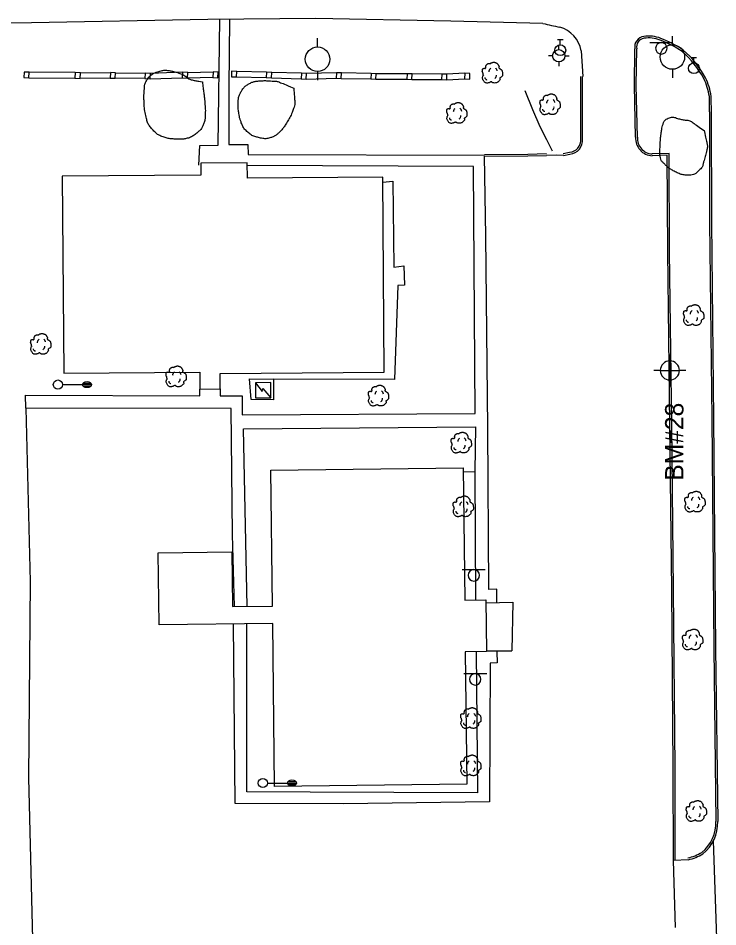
# Model space of a CAD drawing. Extents: x 2145380 to 2156929, y 139568 to 149130.
# Drawn here: x 2150488.9 to 2150717.1, y 141353.6 to 141649.9 of the extents above; entities that cross this region are included whole.
import ezdxf

# ---------------------------------------------------------------- set-up
doc = ezdxf.new("R2010")
doc.units = 0
for name, color, linetype in [('Default', 7, 'Continuous'), ('SURV_Benchmark', 7, 'Continuous'), ('SURV_Text', 7, 'Continuous'), ('TOPO_Asphalt', 7, 'Continuous'), ('TOPO_Building', 7, 'Continuous'), ('TOPO_Concrete', 7, 'Continuous'), ('TOPO_Curb Back', 7, 'Continuous'), ('TOPO_Flowline', 7, 'Continuous'), ('TOPO_Light Pole', 7, 'Continuous'), ('TOPO_Misc', 7, 'Continuous'), ('TOPO_Power Pole', 7, 'Continuous'), ('TOPO_Sidewalk', 7, 'Continuous'), ('TOPO_Sign', 7, 'Continuous'), ('TOPO_Tree', 7, 'Continuous'), ('TOPO_Tree Line', 7, 'Continuous'), ('TOPO_Wall Freestanding', 7, 'Continuous'), ('TOPO_Water Fire Hydrant', 7, 'Continuous'), ('TOPO_Water Valve', 7, 'Continuous')]:
    doc.layers.add(name, color=color, linetype=linetype)

# ---------------------------------------------------------------- blocks, each defined once
blk = doc.blocks.new('LP')
at = {"layer": 'TOPO_Light Pole'}
blk.add_line((3.81, 0), (20.32, 0), dxfattribs=at)
for points in [[(20.32, 0), (27.94, 0)], [(20.32, 0), (23.5, 0)], [(20.83, 1.27), (27.43, 1.27)], [(20.83, 1.27), (23.5, 1.27)], [(23.71, 1.27), (27.43, 1.27)], [(23.71, 0), (27.94, 0)], [(20.83, -1.27), (27.43, -1.27)], [(20.83, -1.27), (23.5, -1.27)], [(23.71, -1.27), (27.43, -1.27)]]:
    blk.add_lwpolyline(points, dxfattribs=at)
blk.add_circle((0, 0), 3.81, dxfattribs=at)
blk.add_ellipse((24.13, 0), major_axis=(3.81, 0), ratio=0.666667, dxfattribs=at)
blk = doc.blocks.new('FIRHYD')
at = {"layer": 'TOPO_Water Fire Hydrant'}
for p, q in [((0, 10.2), (0, 17.3)), ((10.2, 0), (17.3, 0)), ((-10.2, 0), (-17.3, 0)), ((0, -10.2), (0, -17.3))]:
    blk.add_line(p, q, dxfattribs=at)
blk.add_circle((0, 0), 10.2, dxfattribs=at)
blk = doc.blocks.new('TREE')
at = {"layer": 'TOPO_Tree'}
for points in [[(-14.1, -0.4), (-14.2, 0.5), (-14.4, 1.4), (-14.6, 2.3), (-14.8, 3.2), (-15.5, 4), (-15.7, 4.9), (-15.8, 5.6), (-15.7, 6.3), (-15.7, 7), (-15.6, 7.9), (-15.7, 8.8), (-15.1, 9.7), (-14.6, 10.4), (-13.8, 10.5), (-13, 10.7), (-12.2, 11), (-11.1, 10), (-10.4, 10.7), (-9.4, 11.7), (-10.3, 13.3), (-9.8, 14.4), (-9.6, 15.1), (-9.3, 15.9), (-8.8, 16.5), (-8.2, 17.3), (-7.5, 17.7), (-6.7, 18.1), (-6.1, 18.4), (-5.6, 18.6), (-5.1, 18.7), (-4.5, 18.7), (-4, 18.5), (-3.5, 18.1)], [(-3.5, 17.6), (-3.1, 18.3), (-2.6, 18.8), (-1.9, 19.2), (-1, 19.7), (-0.2, 20), (0.7, 20.2), (1.6, 20.5), (2.5, 20.8), (3.4, 20.8), (4.1, 20.7), (4.8, 20.5), (5.5, 20.2), (6.4, 19.9), (7.3, 19.7), (8.2, 19.2), (9.4, 18.4), (10, 17.2), (10.8, 16), (11.2, 15.3), (11.6, 14.6), (11.9, 13.9), (12.2, 13.1), (11.4, 12), (11.9, 11.2), (12, 11), (12.2, 10.9), (12.4, 10.7), (12.9, 10.4), (13.5, 10), (14, 9.7), (14.7, 9.2), (15.4, 8.7), (16.1, 8.1), (16.7, 7.5), (16.9, 6.7), (17.1, 6), (17.6, 4.4), (17.7, 2.8), (17.7, 1.2), (17.7, -0.2), (17.8, -2.2), (16.6, -3), (15.5, -3.8), (14.3, -4.6), (13.2, -5.3)], [(13.2, -5.3), (13.3, -5.8), (13.4, -6.3), (13.4, -6.7), (13.8, -8.5), (12.2, -10), (10.8, -11.5), (10, -12.3), (9.1, -12.8), (8.2, -13.1), (6, -13.8), (3.3, -13.6), (1.3, -13.1), (0.5, -12.9), (-0.1, -11.4), (-0.8, -11.5), (-2, -11.6), (-3.3, -12.8), (-4.5, -13.1), (-6.1, -13.5), (-7.8, -14), (-9.3, -13.6), (-11.4, -13.1), (-12.8, -11.4), (-14.1, -9.4), (-15.3, -7.3), (-15.6, -5.1), (-15.1, -3), (-14.9, -1.9), (-13.9, -0.8), (-13.5, 0.1)], [(-4.2, 5.1), (-4.5, 6.1), (-4.3, 7.2), (-3.8, 8.2), (-3.3, 9.3), (-2.7, 10.3), (-1.6, 11)], [(5.9, 11.2), (6.5, 10.7), (7, 10.2), (7.4, 9.5), (7.9, 8.6), (8.3, 7.6), (8.5, 6.6)], [(-11.4, -4.5), (-11.5, -5.4), (-11, -6.3), (-10.1, -7.2), (-9.3, -8), (-8.5, -8.3), (-7.7, -8.1)], [(4.8, -6.3), (5.7, -5.7), (6.3, -4.9), (6.8, -3.9), (7.4, -2.8), (7.6, -1.7), (7.5, -0.6)]]:
    blk.add_open_spline(points, degree=3, dxfattribs=at)
blk = doc.blocks.new('POWPOL')
at = {"layer": 'TOPO_Power Pole'}
for p, q in [((0, 10.16), (0, 17.34)), ((0, -10.16), (0, -17.34))]:
    blk.add_line(p, q, dxfattribs=at)
blk.add_circle((0, 0), 10.16, dxfattribs=at)
blk = doc.blocks.new('WATVAL')
at = {"layer": 'Default'}
for p, q in [((-2.25, 9), (2.25, 9)), ((0, 4.5), (0, 9))]:
    blk.add_line(p, q, dxfattribs=at)
blk.add_circle((0, 0), 4.5, dxfattribs=at)
blk = doc.blocks.new('BM')
at = {"layer": 'SURV_Benchmark'}
for p, q in [((0, 2.49), (0, 4.15)), ((-2.49, 0), (-4.16, 0)), ((4.16, 0), (2.49, 0)), ((0, -4.16), (0, -2.49))]:
    blk.add_line(p, q, dxfattribs=at)
for points in [[(0, 2.49), (0, 2.49), (0, 0), (2.49, 0), (2.49, 0), (2.49, 0)], [(0, 2.49), (0, 2.49), (0, 0), (2.49, 0), (2.49, 0), (2.49, 0), (2.49, 0)], [(-2.5, 0), (-2.49, 0), (0, 0), (0, -2.49), (0, -2.49)], [(-2.5, 0), (-2.49, 0), (0, 0), (0, -2.49), (0, -2.49)]]:
    blk.add_lwpolyline(points, dxfattribs=at)
for start, end in [(90.0638, 180.0068), (0.0638, 90.0068), (0.0638, 90.0068), (180.0638, 270.0068), (180.0638, 270.0068), (269.9472, 359.9927)]:
    blk.add_arc((0, 0), 2.5, start, end, dxfattribs=at)

msp = doc.modelspace()

# ---------------------------------------------------------------- linework, layer by layer
at = {"layer": 'TOPO_Asphalt'}
for p, q in [((2150650.27, 141459.46), (2150649.88, 141443.53)), ((2150717.09, 141340.93), (2150715.71, 141381.66)), ((2150707.51, 141375.44), (2150702.61, 141375.22)), ((2150703.25, 141353.37), (2150702.61, 141375.22))]:
    msp.add_line(p, q, dxfattribs=at)
for points in [[(2150173.54, 141646.08), (2150188.55, 141646.69), (2150232.35, 141647.37), (2150285.09, 141647.5), (2150334.75, 141647.84), (2150374.92, 141648.5), (2150418.39, 141648.61), (2150460.06, 141648.31), (2150493.23, 141648.46), (2150550.78, 141649.53), (2150586.03, 141649.89), (2150630.05, 141649.07), (2150660.05, 141648.21)], [(2150672.55, 141639.26), (2150673.03, 141630.89)], [(2150645.07, 141459.3), (2150645.04, 141463.69), (2150642.45, 141463.61), (2150642.12, 141516.18), (2150641.45, 141578.89), (2150641.05, 141604.88)], [(2150666.75, 141605.15), (2150664.55, 141605.2), (2150661.27, 141605.11)], [(2150559.44, 141458.02), (2150558.77, 141481.57), (2150558.4, 141522.63), (2150491.39, 141522.67), (2150492.76, 141466.17), (2150492.26, 141402.2), (2150493.85, 141336.4), (2150493.9, 141335.26), (2150500.21, 141335.3)], [(2150645.07, 141443.2), (2150645.18, 141439.69), (2150642.81, 141439.61), (2150642.68, 141394.39), (2150595.05, 141393.64), (2150559.62, 141393.75), (2150559.16, 141452.36)]]:
    msp.add_lwpolyline(points, dxfattribs=at)
for centre, radius, start, end in [((2150680.45, 141727.07), 81.46, 255.4956, 259.4775), ((2150662.63, 141637.31), 10.12, 11.1443, 73.0742)]:
    msp.add_arc(centre, radius, start, end, dxfattribs=at)
at = {"layer": 'TOPO_Building'}
for points in [[(2150554.78, 141528.99), (2150554.74, 141534.03), (2150608.32, 141534.44), (2150607.83, 141598.09), (2150563.64, 141597.76), (2150563.6, 141602.76), (2150548.41, 141602.64), (2150548.44, 141598.72), (2150503.24, 141598.38), (2150503.72, 141534.09), (2150548.12, 141534.43), (2150548.16, 141528.94)], [(2150635.19, 141400.05), (2150572.54, 141399.32), (2150571.91, 141452.51), (2150534.84, 141452.08), (2150534.56, 141475.56), (2150558.55, 141475.84), (2150558.75, 141458.01), (2150571.79, 141458.16), (2150571.27, 141502.48), (2150634.07, 141503.21), (2150634.57, 141460.14), (2150641.48, 141460.22), (2150641.67, 141443.33), (2150634.69, 141443.25)]]:
    msp.add_lwpolyline(points, close=True, dxfattribs=at)
at = {"layer": 'TOPO_Concrete'}
msp.add_lwpolyline([(2150572.17, 141532.18), (2150572.13, 141525.43), (2150564.9, 141525.58), (2150564.29, 141532.31), (2150572.15, 141532.17)], dxfattribs=at)
at = {"layer": 'TOPO_Curb Back'}
for points in [[(2150690.29, 141611.06), (2150689.91, 141627.9), (2150690.06, 141639.88)], [(2150690.89, 141611.05), (2150690.51, 141627.91), (2150690.67, 141639.93)], [(2150672.41, 141610.47), (2150672.41, 141630.89)], [(2150673.01, 141610.49), (2150673.01, 141630.89)], [(2150714.39, 141619.33), (2150714.4, 141583.25), (2150715.13, 141519.34), (2150715.76, 141444.45), (2150716.51, 141387.95)], [(2150714.99, 141619.33), (2150715, 141583.25), (2150715.73, 141519.35), (2150716.36, 141444.46), (2150717.11, 141387.96)], [(2150641.05, 141605.48), (2150655.1, 141605.56), (2150661.25, 141605.71)], [(2150641.05, 141604.88), (2150655.11, 141604.96), (2150661.27, 141605.11)], [(2150666.64, 141605.74), (2150668.78, 141606.15)], [(2150666.75, 141605.15), (2150668.86, 141605.55)], [(2150702.61, 141375.22), (2150702.55, 141405.47), (2150702.1, 141463.46), (2150701.51, 141517.28), (2150700.78, 141573.79), (2150700.62, 141605.17), (2150695.72, 141605.01)], [(2150703.21, 141375.22), (2150703.15, 141405.47), (2150702.7, 141463.47), (2150702.11, 141517.29), (2150701.38, 141573.8), (2150701.21, 141605.79), (2150695.73, 141605.61)]]:
    msp.add_lwpolyline(points, dxfattribs=at)
for centre, radius, start, end in [((2150693.45, 141640.51), 3.45, 98.2377, 190.5026), ((2150694.66, 141634.03), 10.03, 67.6279, 99.7384), ((2150694.66, 141634.03), 9.43, 67.5689, 99.7914), ((2150693.45, 141640.51), 2.85, 98.0875, 191.6329), ((2150686.32, 141610.87), 34.04, 55.7908, 69.4722), ((2150686.32, 141610.87), 34.64, 55.7299, 69.4572), ((2150684.11, 141614.61), 32.43, 28.6996, 48.8254), ((2150684.1, 141614.61), 33.03, 28.6724, 48.8876), ((2150694.23, 141621.39), 20.33, 8.3067, 25.6492), ((2150694.23, 141621.39), 20.92, 8.2114, 25.6956), ((2150591.82, 141620.53), 122.58, 359.438, 1.772), ((2150591.73, 141620.53), 123.27, 359.4398, 1.7866), ((2150696.01, 141610.73), 5.73, 176.6666, 267.1133), ((2150696.01, 141610.73), 5.13, 176.4023, 266.8393), ((2150668.43, 141610.12), 3.99, 274.9481, 4.9483), ((2150668.43, 141610.12), 4.59, 275.3455, 4.6133), ((2150703.94, 141387.58), 12.57, 309.1883, 1.6573), ((2150703.94, 141387.58), 13.17, 308.9772, 1.6372), ((2150703.25, 141392.81), 17.28, 283.7553, 299.9752), ((2150703.26, 141392.8), 17.87, 283.7547, 300.1312)]:
    msp.add_arc(centre, radius, start, end, dxfattribs=at)
at = {"layer": 'TOPO_Flowline'}
msp.add_lwpolyline([(2150663.17, 141606.53), (2150661.36, 141610.26), (2150659.16, 141614.46), (2150656.8, 141620.01), (2150654.23, 141626.18)], dxfattribs=at)
at = {"layer": 'TOPO_Misc'}
for points in [[(2150571.31, 141526.04), (2150571.31, 141531.03), (2150566.31, 141531.02), (2150566.32, 141526.03), (2150571.31, 141526.04)], [(2150566.31, 141531.02), (2150568.42, 141528.16), (2150568.65, 141529.1), (2150571.31, 141526.04)]]:
    msp.add_lwpolyline(points, dxfattribs=at)
at = {"layer": 'TOPO_Sidewalk'}
msp.add_line((2150563.5, 141397.6), (2150563.52, 141452.41), dxfattribs=at)
for points in [[(2150547.82, 141601.99), (2150548.14, 141608.38), (2150554.11, 141608.47), (2150554.64, 141649.57)], [(2150557.84, 141649.6), (2150557.55, 141627.25), (2150557.64, 141608.72), (2150563.81, 141608.65), (2150563.9, 141605.42), (2150641.05, 141605.18)], [(2150554.78, 141528.99), (2150554.79, 141526.72), (2150561.97, 141526.73), (2150561.93, 141520.49), (2150637.99, 141520.97), (2150637.41, 141601.48), (2150563.61, 141601.9)], [(2150491.41, 141522.68), (2150491.29, 141526.9), (2150548.18, 141526.77), (2150548.16, 141528.94)], [(2150563.55, 141458.07), (2150562.39, 141515.93), (2150638.07, 141516.67), (2150637.86, 141502.1)]]:
    msp.add_lwpolyline(points, dxfattribs=at)
at = {"layer": 'TOPO_Sign'}
for points in [[(2150694.94, 141641.94), (2150702.43, 141641.95)], [(2150698.69, 141641.94), (2150698.69, 141641.94)], [(2150696.82, 141640.07), (2150696.82, 141640.07)], [(2150698.69, 141638.2), (2150698.69, 141638.2)], [(2150700.55, 141640.07), (2150700.55, 141640.07)], [(2150633.76, 141470.07), (2150641.25, 141470.08)], [(2150637.51, 141470.07), (2150637.51, 141470.07)], [(2150635.64, 141468.21), (2150635.64, 141468.21)], [(2150637.51, 141466.34), (2150637.51, 141466.34)], [(2150639.38, 141468.21), (2150639.38, 141468.21)], [(2150634.23, 141436.17), (2150641.73, 141436.18)], [(2150637.98, 141436.17), (2150637.98, 141436.17)], [(2150636.11, 141434.3), (2150636.11, 141434.3)], [(2150639.85, 141434.3), (2150639.85, 141434.3)], [(2150637.98, 141432.43), (2150637.98, 141432.43)]]:
    msp.add_lwpolyline(points, dxfattribs=at)
for centre, start, end in [((2150698.69, 141640.07), 90, 180), ((2150698.69, 141640.07), 360, 90), ((2150698.69, 141640.07), 180, 270), ((2150698.69, 141640.07), 270, 0), ((2150637.51, 141468.21), 90, 180), ((2150637.51, 141468.21), 360, 90), ((2150637.51, 141468.21), 180, 270), ((2150637.51, 141468.21), 270, 0), ((2150637.98, 141434.3), 90, 180), ((2150637.98, 141434.3), 360, 90), ((2150637.98, 141434.3), 180, 270), ((2150637.98, 141434.3), 270, 0)]:
    msp.add_arc(centre, 1.87, start, end, dxfattribs=at)
at = {"layer": 'TOPO_Tree Line'}
for points in [[(2150548.98, 141629.08), (2150548.01, 141629.27), (2150547.04, 141629.46), (2150546.06, 141629.66), (2150544.51, 141629.96), (2150543.31, 141631.22), (2150541.82, 141631.8), (2150540.81, 141632.19), (2150539.77, 141632.45), (2150538.73, 141632.67), (2150537.6, 141632.91), (2150536.4, 141632.94), (2150535.25, 141632.65), (2150533.39, 141632.19), (2150531.65, 141631.15), (2150530.67, 141629.34), (2150530.15, 141628.36), (2150530.07, 141627.38), (2150530, 141626.36), (2150529.93, 141625.29), (2150529.88, 141624.23), (2150529.92, 141623.16), (2150529.98, 141621.12), (2150530.23, 141619.1), (2150530.73, 141617.08), (2150531.04, 141615.82), (2150531.65, 141614.74), (2150532.58, 141613.71), (2150533.73, 141612.43), (2150534.99, 141611.55), (2150536.56, 141611.05), (2150537.85, 141610.64), (2150539.14, 141610.52), (2150540.44, 141610.45), (2150541.51, 141610.4), (2150542.6, 141610.39), (2150543.67, 141610.63), (2150545.11, 141610.97), (2150546.29, 141611.73), (2150547.47, 141612.72), (2150548.19, 141613.31), (2150548.76, 141613.91), (2150549.12, 141614.75), (2150549.63, 141615.92), (2150549.87, 141617.11), (2150549.9, 141618.33), (2150549.92, 141619.28), (2150549.95, 141620.23), (2150549.86, 141621.17), (2150549.77, 141622.26), (2150549.69, 141623.35), (2150549.55, 141624.43), (2150549.36, 141625.98), (2150549.17, 141627.53), (2150548.98, 141629.08), (2150548.98, 141629.08)], [(2150578.75, 141627.12), (2150577.18, 141627.76), (2150575.61, 141628.4), (2150574.04, 141629.04), (2150573.19, 141629.39), (2150572.23, 141629.36), (2150571.32, 141629.43), (2150569.88, 141629.53), (2150568.43, 141629.51), (2150566.99, 141629.37), (2150565.89, 141629.26), (2150564.88, 141628.91), (2150563.87, 141628.31), (2150562.93, 141627.75), (2150562.27, 141627.05), (2150561.71, 141626.1), (2150561.12, 141625.1), (2150560.75, 141624.08), (2150560.67, 141623), (2150560.56, 141621.6), (2150560.65, 141620.16), (2150560.87, 141618.76), (2150561.02, 141617.86), (2150561.22, 141616.99), (2150561.54, 141616.12), (2150562.02, 141614.82), (2150562.66, 141613.73), (2150563.75, 141612.72), (2150564.82, 141611.73), (2150566.03, 141611.29), (2150567.32, 141610.96), (2150568.62, 141610.62), (2150570.05, 141610.52), (2150571.33, 141610.95), (2150572.24, 141611.25), (2150573.06, 141611.72), (2150573.79, 141612.41), (2150574.73, 141613.3), (2150575.46, 141614.21), (2150576.15, 141615.28), (2150577.12, 141616.79), (2150577.93, 141618.27), (2150578.57, 141619.97), (2150578.9, 141620.83), (2150579.21, 141621.69), (2150579.13, 141622.58), (2150579.01, 141624.09), (2150578.88, 141625.61), (2150578.75, 141627.12), (2150578.75, 141627.12)], [(2150712.61, 141613.23), (2150711.3, 141614.15), (2150710, 141615.07), (2150708.69, 141616), (2150707.73, 141616.68), (2150706.4, 141616.61), (2150705.24, 141616.87), (2150703.97, 141617.15), (2150702.64, 141617.77), (2150701.38, 141617.39), (2150699.78, 141616.92), (2150699.01, 141614.83), (2150698.75, 141613.19), (2150698.57, 141612.1), (2150698.44, 141611.01), (2150698.37, 141609.91), (2150698.31, 141609.05), (2150698.27, 141608.19), (2150698.23, 141607.34), (2150698.19, 141606.34), (2150698.17, 141605.34), (2150698.38, 141604.34), (2150698.57, 141603.44), (2150699.24, 141602.78), (2150699.93, 141602.12), (2150700.83, 141601.25), (2150701.71, 141600.63), (2150702.83, 141600.01), (2150704.13, 141599.29), (2150705.47, 141598.82), (2150706.78, 141598.72), (2150708.33, 141598.59), (2150709.95, 141599.14), (2150711.33, 141600.58), (2150712.24, 141601.54), (2150712.31, 141602.51), (2150712.64, 141603.55), (2150712.9, 141604.35), (2150713.15, 141605.14), (2150713.33, 141605.96), (2150713.55, 141607), (2150713.81, 141608.09), (2150713.57, 141609.12), (2150713.25, 141610.49), (2150712.93, 141611.86), (2150712.61, 141613.23)]]:
    msp.add_open_spline(points, degree=3, dxfattribs=at)
at = {"layer": 'TOPO_Wall Freestanding'}
for p, q in [((2150507.5, 141632.13), (2150492.47, 141632.24)), ((2150509.17, 141632.04), (2150518.99, 141632.17)), ((2150520.66, 141632.08), (2150530.32, 141631.99)), ((2150542.51, 141632.24), (2150531.99, 141631.9)), ((2150544.18, 141632.15), (2150552.47, 141632.36)), ((2150569.92, 141632.31), (2150560.19, 141632.52)), ((2150581.26, 141631.92), (2150571.59, 141632.22)), ((2150592.7, 141632.11), (2150582.93, 141631.84)), ((2150604, 141631.87), (2150594.37, 141632.02)), ((2150615.75, 141631.79), (2150605.67, 141631.78)), ((2150627.08, 141631.68), (2150617.42, 141631.7)), ((2150634.58, 141631.93), (2150628.75, 141631.59)), ((2150492.38, 141630.44), (2150507.4, 141630.33)), ((2150518.9, 141630.37), (2150509.07, 141630.24)), ((2150530.23, 141630.19), (2150520.57, 141630.28)), ((2150531.9, 141630.1), (2150542.41, 141630.44)), ((2150552.37, 141630.56), (2150544.08, 141630.35)), ((2150560.09, 141630.72), (2150569.82, 141630.51)), ((2150571.49, 141630.42), (2150581.17, 141630.12)), ((2150582.84, 141630.03), (2150592.61, 141630.31)), ((2150594.28, 141630.22), (2150603.9, 141630.07)), ((2150605.57, 141629.98), (2150615.66, 141629.99)), ((2150617.33, 141629.9), (2150626.99, 141629.88)), ((2150628.66, 141629.79), (2150634.49, 141630.13)), ((2150641.49, 141459.2), (2150650.27, 141459.46)), ((2150641.67, 141443.54), (2150649.88, 141443.53))]:
    msp.add_line(p, q, dxfattribs=at)
for points in [[(2150492.47, 141632.24), (2150490.8, 141632.33), (2150490.71, 141630.52), (2150492.38, 141630.44)], [(2150509.17, 141632.04), (2150507.5, 141632.13), (2150507.4, 141630.33), (2150509.07, 141630.24)], [(2150520.66, 141632.08), (2150518.99, 141632.17), (2150518.9, 141630.37), (2150520.57, 141630.28)], [(2150531.99, 141631.9), (2150530.32, 141631.99), (2150530.23, 141630.19), (2150531.9, 141630.1)], [(2150544.18, 141632.15), (2150542.51, 141632.24), (2150542.41, 141630.44), (2150544.08, 141630.35)], [(2150554.14, 141632.27), (2150552.47, 141632.36), (2150552.37, 141630.56), (2150554.04, 141630.47)], [(2150560.19, 141632.52), (2150558.52, 141632.61), (2150558.42, 141630.81), (2150560.09, 141630.72)], [(2150571.59, 141632.22), (2150569.92, 141632.31), (2150569.82, 141630.51), (2150571.49, 141630.42)], [(2150582.93, 141631.84), (2150581.26, 141631.92), (2150581.17, 141630.12), (2150582.84, 141630.03)], [(2150594.37, 141632.02), (2150592.7, 141632.11), (2150592.61, 141630.31), (2150594.28, 141630.22)], [(2150605.67, 141631.78), (2150604, 141631.87), (2150603.9, 141630.07), (2150605.57, 141629.98)], [(2150617.42, 141631.7), (2150615.75, 141631.79), (2150615.66, 141629.99), (2150617.33, 141629.9)], [(2150628.75, 141631.59), (2150627.08, 141631.68), (2150626.99, 141629.88), (2150628.66, 141629.79)], [(2150636.25, 141631.84), (2150634.58, 141631.93), (2150634.49, 141630.13), (2150636.16, 141630.04)]]:
    msp.add_lwpolyline(points, close=True, dxfattribs=at)
for points in [[(2150607.85, 141596.42), (2150611.11, 141596.69), (2150611.47, 141568.69), (2150614.67, 141569.11), (2150614.91, 141562.81), (2150612.76, 141562.76), (2150611.62, 141532.09), (2150572.15, 141532.17)], [(2150634.08, 141501.92), (2150637.86, 141502.1), (2150638.01, 141460.18)], [(2150638.33, 141443.29), (2150638.72, 141397.29), (2150584.18, 141397.48), (2150563.5, 141397.6)]]:
    msp.add_lwpolyline(points, dxfattribs=at)

# ---------------------------------------------------------------- block references
at = {"layer": 'SURV_Benchmark', "xscale": 1.25, "yscale": 1.25}
msp.add_blockref('BM', (2150701.47, 141535.01), dxfattribs=at)
at = {"layer": 'TOPO_Light Pole', "xscale": 0.39370000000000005, "yscale": 0.3937000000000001}
for p in [(2150501.84, 141530.4), (2150568.68, 141400.46)]:
    msp.add_blockref('LP', p, dxfattribs=at)
at = {"layer": 'TOPO_Power Pole', "xscale": 0.39370000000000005, "yscale": 0.3937000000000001}
for p in [(2150702.28, 141637.23), (2150586.53, 141636.51)]:
    msp.add_blockref('POWPOL', p, dxfattribs=at)
at = {"layer": 'TOPO_Tree', "xscale": 0.19685000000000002, "yscale": 0.19685000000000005}
for p in [(2150643.39, 141631.44), (2150662.19, 141621.13), (2150631.79, 141618.31), (2150709.05, 141552.39), (2150496.05, 141543), (2150540.22, 141532.39), (2150606.23, 141526.13), (2150633.23, 141510.8), (2150709.47, 141491.55), (2150633.88, 141490.02), (2150708.71, 141446.59), (2150636.36, 141420.98), (2150636.36, 141405.54), (2150709.92, 141390.68)]:
    msp.add_blockref('TREE', p, dxfattribs=at)
at = {"layer": 'TOPO_Water Fire Hydrant', "xscale": 0.19685000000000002, "yscale": 0.19685000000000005}
msp.add_blockref('FIRHYD', (2150665.24, 141637.64), dxfattribs=at)
at = {"layer": 'TOPO_Water Valve', "xscale": 0.39370000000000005, "yscale": 0.3937000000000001}
for p in [(2150665.72, 141639.44), (2150709.31, 141633.57)]:
    msp.add_blockref('WATVAL', p, dxfattribs=at)

# ---------------------------------------------------------------- texts
at = {"layer": 'SURV_Text'}
msp.add_text('BM#28', height=6, rotation=90, dxfattribs=at).set_placement((2150705.9, 141499.06))

doc.saveas('drawing.dxf')
